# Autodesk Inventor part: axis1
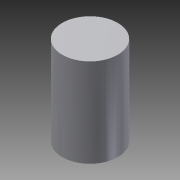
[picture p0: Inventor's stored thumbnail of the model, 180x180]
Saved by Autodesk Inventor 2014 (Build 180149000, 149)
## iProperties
Created: 2009-11
Part Number: axis1
Document SubType Name: Modeling
Designer: pokornp
Density: 1 g/cm^3
Material: Generic
Appearance: Default
Author: pokornp
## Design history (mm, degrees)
sketch "Sketch1"
  geometry: C1 r 50 at (0, 0); 1 further point
  constraints: 1 centre point, 1 coincident
  dimensions: "d0" = 100 diameter of C1
extrude "Extrusion1" new body sketch "Sketch1" distance "d1" = 160; taper "d2" = 0 deg
body "Solid1"
